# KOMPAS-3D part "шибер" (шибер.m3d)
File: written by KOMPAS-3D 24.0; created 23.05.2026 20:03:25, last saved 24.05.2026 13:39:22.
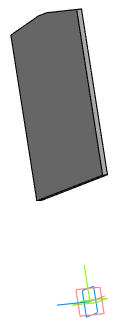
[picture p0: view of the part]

Document properties: Автор: R2D2; Полное имя файла: E:\Работа\Зайцев\GVKR1331E-1W-Fb-2P Задвижка шиберная DN.ru Ду50-300 Ру16-10-6\исходные материалы\DN250\шибер.m3d

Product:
- Part/product: шибер
    Масса: 7.348726
    Раздел спецификации: Прочие изделия
    Примечание: D040-08800

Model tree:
1. Эскиз:5  (with: Грань.Элемент выдавливания:1, Вершина.Элемент выдавливания:15)
2. Элемент выдавливания:6
     Расстояние 1 = 10

Referenced files in E:\Работа\Зайцев\GVKR1331E-1W-Fb-2P Задвижка шиберная DN.ru Ду50-300 Ру16-10-6\исходные материалы\DN250\: GVKR1331E-1W-Fb-2P Задвижка шиберная с выдвижным штоком DN.ru Ду250 Ру10.a3d
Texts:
  Затвор дисковый DN.ru Ду Ру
